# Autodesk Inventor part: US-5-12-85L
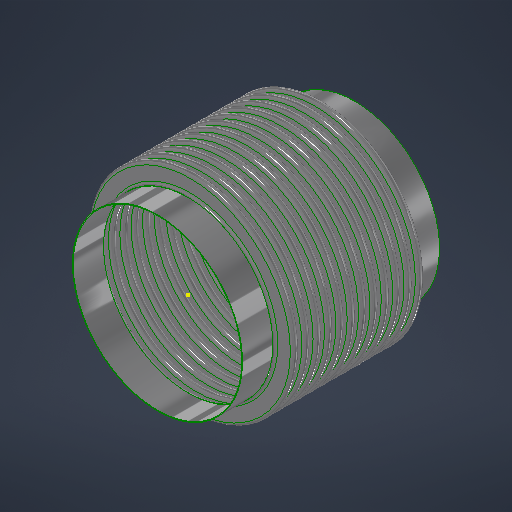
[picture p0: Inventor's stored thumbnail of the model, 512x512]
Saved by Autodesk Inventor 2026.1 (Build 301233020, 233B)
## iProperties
Category: 24 GA (0.024 THICK)
RuleStatus: InUse
Created: 2026-07
Part Number: US-5-12-85L
Project: =STOCK BELLOWS: <Stock Number><SFILL>
Material: ASTM A240-304
Description: =STOCK BELLOWS: <Stock Number>, <SID_> I.D., <SOD_> O.D., <SPLY_> PLY, <Category>, <SNET_CONS> CONS.<PITCH_><STANGENT_> TANGENT<SFILL>
Document SubType Name: Sheet Metal
Designer: LC
Stock Number: U.S-5-12-85L
Surface Area: 659.127 cm^2
Volume: 56.61 cm^3
Sheet Metal Rule: Default
Appearance: STAINLESS STEEL
NET_TUBE: 3.428
COUNTER: 1.500
PBAR: 1.214
PSET: 5.356
PLY: 2
CONS: 2
THK: 0.036
ID: 4.500
OD: 5.500
CONS_: 2
TANGENT: 0.500
PITCH: 0.375
BELLOWS_UPSET: 0.000
NET_CONS: 2
S_CONS: 0
Description_Units: 0
ID_M: 114.30 mm
OD_M: 139.70 mm
THK_M: 0.91 mm
ID_U: 4.500 in
OD_U: 5.500 in
THK_U: 0.036 in
TANGENT2: 0.500
d79: 1.000
d82: 1.000
d83: 26.000
d84: 24.000
d80: 2.571
d81: 10
SID: 2.375
SCONS_: 12
SPITCH: 0.250
SBELLOWS_UPSET: 0.000
SNET_CONS: 12
SS_CONS: 0
SCONS: 8
d174: 8
d177: 0.018
d178: 2.375
d179: 3.000
d180: 0.375
d181: 1.000
d182: 0.000
d190: 8
d191: 1
d192: 1
d193: 8
d194: 0
PART_NUMBER: U.S-5-12-85L
PRESSURE: 85
SIZE: 5.00
STANGENT_: 1.000
d214: 8
d217: 0.030
d218: 6.625
d219: 8.125
d220: 0.500
d221: 1.000
d222: 0.000
d230: 8
d231: 1
d232: 1
d233: 8
d234: 0
STANGENT: 4.000
SPLY_: 1
STHK_: 0.024
SID_: 5.563
SOD_: 6.813
SPITCH_: 0.375
STANGENT__: 1.000
SBELLOWS_UPSET_: 0.000
SDIFF_TAN: 1.000
TAN_TO_TAN: 0.750 in
d252: 2
d275: 2
d287: 0.050
d289: 0.500
d290: 0.000
d263: 2
d265: 1
d268: 2
d269: 0
d286: 2
d288: 1
d291: 2
d292: 0
SOD_NECK: 5 5/8
CFILL: .
SFILL: .
PITCH_: =, <SPITCH_> PITCH,
SREROLL: 0.750
MATTABLE: 20 GA (0.036 THICK)
MESH: ,
CSECT: 2
Author: LC
Keywords: 20 GA (0.036 THICK)
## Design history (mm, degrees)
sketch "Sketch2"
  geometry: L1 (0, -183.595)-(0, 600.956) reference; L2 (58.979, 0)-(57.15, 0); L3 (60.446, -1.467)-(66.554, -1.467); L4 (60.446, -3.296)-(66.554, -3.296); L5 (66.554, -8.058)-(60.446, -8.058); L6 (66.554, -6.229)-(60.446, -6.229); L7 (58.979, -9.525)-(57.15, -9.525); L8 (60.446, 0)-(60.446, -9.525); L9 (66.554, -4.762)-(69.85, -4.763); L10 (57.15, 0)-(57.15, -9.525); L11 (20.376, 102.841)-(20.376, 101.926); L12 (58.262, 488.877)-(58.262, 349.177); L13 (58.262, 479.352)-(58.262, 339.652); L14 (93.133, -58.817)-(93.133, -71.517); L15 (118.746, -66.401)-(118.746, -66.401); L16 (66.554, -6.229)-(66.554, -8.058); L17 (60.446, -6.229)-(60.446, -8.058); L18 (60.446, -7.144)-(66.554, -7.144); L19 (69.85, 0)-(69.85, -9.525); L20 (-66.554, -6.229)-(-66.554, -8.058); L21 (-66.554, -1.467)-(-60.446, -1.467); L22 (-66.554, -3.296)-(-60.446, -3.296); L23 (-60.446, -6.229)-(-66.554, -6.229); L24 (-66.554, -7.144)-(-60.446, -7.144); L25 (-60.446, -8.058)-(-66.554, -8.058); L26 (-60.446, -6.229)-(-60.446, -8.058); L27 (-57.15, -2.522)-(-57.15, -12.047); L28 (-60.446, -4.763)-(-57.15, -4.763); L29 (-66.554, 3.828)-(-66.554, -9.525); L30 (-68.021, 0)-(-69.85, 0); L31 (-69.85, 0)-(-69.85, -9.525); L32 (-68.021, -9.525)-(-69.85, -9.525); A1 r 1.467 centre (60.446, 0) between (58.979, 0) and (60.446, -1.467); A2 r 3.296 centre (60.446, 0) between (57.15, 0) and (60.446, -3.296); A3 r 3.296 centre (66.554, -4.762) between (66.554, -8.058) and (66.554, -1.467); A4 r 1.467 centre (66.554, -4.762) between (66.554, -6.229) and (66.554, -3.296); A5 r 1.467 centre (60.446, -9.525) between (60.446, -8.058) and (58.979, -9.525); A6 r 3.296 centre (60.446, -9.525) between (60.446, -6.229) and (57.15, -9.525); A7 r 2.381 centre (66.554, -4.762) between (66.554, -7.144) and (68.936, -4.762); A8 r 2.381 centre (60.446, -9.525) between (60.446, -7.144) and (58.064, -9.525); A9 r 1.467 centre (-66.554, -9.525) between (-66.554, -8.058) and (-68.021, -9.525); A10 r 1.467 centre (-60.446, -4.763) between (-60.446, -6.229) and (-60.446, -3.296); A11 r 2.381 centre (-60.446, -4.763) between (-60.446, -7.144) and (-58.064, -4.763); A12 r 3.296 centre (-60.446, -4.763) between (-60.446, -8.058) and (-60.446, -1.467); A13 r 2.381 centre (-66.554, -9.525) between (-66.554, -7.144) and (-68.936, -9.525); A14 r 3.296 centre (-66.554, -9.525) between (-66.554, -6.229) and (-69.85, -9.525); A15 r 1.467 centre (-66.554, 0) between (-68.021, 0) and (-66.554, -1.467); A16 r 3.296 centre (-66.554, 0) between (-69.85, 0) and (-66.554, -3.296); 10 further points
  constraints: 62 end point, 38 point on circle, 20 tangent, 16 centre point, 12 parallel, 9 midpoint, 7 vertical, 6 coincident, 6 concentric, 6 point on line, 4 equal radius, 4 perpendicular, 3 horizontal, 1 collinear, 1 horizontal alignment, 10 other
  dimensions: "THK" = 0.9144 distance of L11.start L11.end; "ID" = 114.3 distance of L11.end point (20.376, -12.374); "OD" = 139.7 distance of L12.start L12.end; "PITCH" = 9.525 distance of L12.start L13.start; "TANGENT" = 12.7 distance of L14.start L14.end; "BELLOWS_UPSET" = 0 distance of L15.start L15.end; "d43" = 114.3 diameter of L10 L1 (= ID); "d44" = 139.7 diameter of L9.end L1 (= OD); "d45" = 1.8288 distance between parallel lines of L5 L6 (computed from THK, PLY); "d46" = 3.29565 radius of A3 (computed from PITCH, THK, PLY); "UPSET_PITCH" = 9.525 distance of L2.end L7.end (derived); "SIDEWALL_ANGLE" = 0 deg angle of L3 L9 (derived); "CON_GAP" = 2.9337 distance of point (60.446, -6.229) point (60.446, -3.296) (derived); "TAN1" = 3.74046 dimension on A8 (derived); "TAN2" = 3.74046 dimension on A7 (derived); "LEG1" = 6.1087 distance of L18.start L18.end (derived); "d278" = 1.8288 distance between parallel lines of L25 L23 (derived); "d279" = 3.29565 radius of A12 (derived); "d280" = 9.525 distance of L30.end L31.end (derived); "d281" = 360 deg dimension on L21 L28 (derived); "d282" = 2.9337 distance of point (-66.554, -6.229) point (-66.554, -3.296) (derived); "d283" = 3.74046 dimension on A13 (derived); "d284" = 3.74046 dimension on A11 (derived); "d285" = 6.1087 distance of L24.start L24.end (derived); "d293" = 114.3 diameter of L27 L1 (derived); "d294" = 139.7 diameter of L31 L1 (derived)
  node "Sketch Rectangular Pattern1" dims "d31" = 25.4, "ID" = 114.3
  node "Sketch Rectangular Pattern2" dims "d39" = 25.4, "PITCH" = 9.525
revolve "CONS" stored, may be unused: angle "d48" = 90 deg
node "BELLOW MIDPLANE"
pattern_linear "Rectangular Pattern2" dims "d52" = 9.525 (= UPSET_PITCH)
sketch "Sketch5"
  geometry: C1 r 58.979 at (0, 0) reference; C2 r 57.15 at (0, 0) reference
extrude "TANGENT" new body sketch "Sketch5" distance "d53" = 12.7 (= TANGENT); taper "d54" = 0 deg
revolve "SAMETAN" stored, may be unused: angle "d65" = 90 deg
revolve "DIFFTAN" stored, may be unused: angle "d70" = 90 deg
sketch "Sketch9"
  geometry: L1 (58.391, 0)-(-58.391, 0) reference; L2 (0, -17.78)-(0, 17.78) reference; L3 (41.708, 0)-(-41.708, 0); L4 (41.708, -11.906)-(41.708, 11.906); L5 (29.008, -11.906)-(29.008, 11.906); L6 (15.418, 11.906)-(15.418, -11.906); L7 (-29.008, -11.906)-(-29.008, 11.906); L8 (-41.708, -11.906)-(-41.708, 11.906); L9 (40.914, -11.906)-(40.914, 11.906); L10 (41.708, -11.906)-(40.914, -11.906); L11 (41.708, 11.906)-(40.914, 11.906); L12 (15.815, 11.906)-(15.022, 11.906); L13 (15.022, 11.906)-(15.022, -11.906); L14 (15.022, -11.906)-(15.815, -11.906); L15 (15.815, -11.906)-(15.815, 11.906); L16 (-15.815, 11.906)-(-15.815, -11.906); L17 (-15.418, 11.906)-(-15.418, -11.906); L18 (-15.815, -11.906)-(-15.022, -11.906); L19 (-15.022, -11.906)-(-15.022, 11.906); L20 (-15.022, 11.906)-(-15.815, 11.906); L21 (-41.708, -11.906)-(-40.914, -11.906); L22 (-40.914, -11.906)-(-40.914, 11.906); L23 (-40.914, 11.906)-(-41.708, 11.906); L24 (-41.708, 11.906)-(-41.708, -11.906); L25 (41.708, -0.397)-(-41.708, -0.397); L26 (-41.708, -0.397)-(-41.708, 0.397); L27 (-41.708, 0.397)-(41.708, 0.397); L28 (41.708, 0.397)-(41.708, -0.397); L29 (-41.708, 11.906)-(41.708, 11.906); L30 (41.708, 11.906)-(41.708, 12.7); L31 (41.708, 12.7)-(-41.708, 12.7); L32 (-41.708, 12.7)-(-41.708, 11.906); L33 (41.708, -11.906)-(-41.708, -11.906); L34 (-41.708, -11.906)-(-41.708, -12.7); L35 (-41.708, -12.7)-(41.708, -12.7); L36 (41.708, -12.7)-(41.708, -11.906); 30 further points
  constraints: 68 end point, 13 midpoint, 13 parallel, 8 horizontal, 7 perpendicular, 6 equal length, 3 point on line, 2 vertical, 14 other
  dimensions: "d115" = 23.8125 distance of L4.start L4.end (derived); "d116" = 12.7 distance between parallel lines of L4 L5 (derived); "d117" = 13.58962 distance between parallel lines of L5 L6 (derived); "d125" = 44.42645 distance between parallel lines of L7 L6 (derived); "d127" = 12.7 distance between parallel lines of L8 L7 (derived); "d128" = 26.28962 distance between parallel lines of L6 L4 (derived); "d130" = 83.41607 distance between parallel lines of L8 L4 (derived); "RULER_THK" = 0.79375 distance between parallel lines of L4 L9; "d135" = 0.79375 distance of L13.end L14.end (derived); "d138" = 30.83684 distance of L13.end L16.end (derived); "d143" = 0.79375 distance of L22.end L8.end (derived); "d144" = 0.79375 distance between parallel lines of L27 L25 (derived)
extrude "RULER" join sketch "Sketch9" distance "d149" = 0.79375 (derived); taper "d150" = 0 deg
extrude "BARS" join sketch "Sketch9" distance "d151" = 0.79375 (derived); taper "d152" = 0 deg
pattern_linear "Rectangular Pattern4" dims "d155" = 30.83684 (derived)
sketch "Sketch13"
  geometry: L1 (93.149, -52.467)-(93.149, -77.867); L2 (71.26, 0)-(70.65, 0); L3 (71.26, -9.525)-(70.65, -9.525); L4 (83.839, -7.449)-(73.336, -7.449); L5 (83.839, -6.839)-(73.336, -6.839); L6 (83.839, -4.763)-(86.525, -4.763); L7 (73.336, -2.076)-(83.839, -2.076); L8 (73.336, 0)-(73.336, -9.525); L9 (70.65, 0)-(70.65, -9.525); L10 (58.254, -341.381)-(58.254, -514.431); L11 (58.254, -350.906)-(58.254, -523.956); L12 (58.254, -369.956)-(58.254, -543.006); L13 (58.254, -379.481)-(58.254, -552.531); L14 (58.254, -389.006)-(58.254, -562.056); L15 (58.254, -398.531)-(58.254, -571.581); L16 (58.254, -408.056)-(58.254, -581.106); L17 (58.254, -360.431)-(58.254, -533.481); L18 (20.376, 102.536)-(20.376, 101.926); L19 (73.336, -2.686)-(83.839, -2.686); L20 (0, -696.234)-(0, 235.664) reference; L21 (-23.752, 0)-(142.514, 0) reference; A1 r 2.076 centre (73.336, 0) between (71.26, 0) and (73.336, -2.076); A2 r 2.076 centre (73.336, -9.525) between (73.336, -7.449) and (71.26, -9.525); A3 r 2.686 centre (73.336, -9.525) between (73.336, -6.839) and (70.65, -9.525); A4 r 2.076 centre (83.839, -4.763) between (83.839, -6.839) and (83.839, -2.686); A5 r 2.686 centre (83.839, -4.763) between (83.839, -7.449) and (83.839, -2.076); A6 r 2.686 centre (73.336, 0) between (70.65, 0) and (73.336, -2.686); 6 further points; 1 other entity
  constraints: 38 end point, 15 point on circle, 9 tangent, 6 centre point, 6 parallel, 5 vertical alignment, 4 point on line, 4 vertical, 3 coincident, 3 concentric, 2 collinear, 2 equal radius, 1 horizontal, 1 perpendicular, 23 other
  dimensions: "SBELLOWS_UPSET_" = 0 distance of point (118.762, -66.401) point (118.762, -66.401); "STOTAL_THK_BELLOW__" = 0.6096 distance between parallel lines of L4 L5 (derived); "d224" = 2.68605 radius of A5 (derived); "d225" = 9.525 distance of L2.end L3.end (derived); "SSIDEWALL_ANGLE_" = 0 deg angle of L7 L6 (derived); "SSCON_GAP_" = 4.1529 distance of point (73.336, -6.839) point (73.336, -2.686) (derived); "d235" = 141.3002 diameter of L9 L20 (derived); "d236" = 173.0502 diameter of L6.end L20 (derived)
  node "Sketch Rectangular Pattern4" dims "d228" = 25.4
  node "Sketch Rectangular Pattern5" dims "d229" = 25.4
revolve "SBELLOW" stored, may be unused: angle "d197" = 90 deg
pattern_linear "Rectangular Pattern5" dims "d204" = 9.525 (derived)
revolve "STANGENT" stored, may be unused: angle "d240" = 90 deg
revolve "SSAMETAN" stored, may be unused: angle "d241" = 90 deg
revolve "SDIFFTAN" stored, may be unused: angle "d246" = 90 deg
revolve "INVCON" stored, may be unused: angle "d295" = 90 deg
pattern_linear "Rectangular Pattern6" dims "d298" = 9.525 (derived)
revolve "INVTANGENT" stored, may be unused: angle "d302" = 90 deg
revolve "INVSAMETAN" stored, may be unused: angle "d307" = 90 deg
revolve "INVDIFFTAN" stored, may be unused: angle "d312" = 90 deg
sketch "ID BELLOW MOUNT CALC"
  geometry: L1 (44.45, 0)-(38.1, 0); L2 (38.1, 0)-(38.1, 12.7); L3 (38.1, 12.7)-(44.45, 12.7); L4 (44.45, 12.7)-(44.45, 0); L5 (36.513, 12.7)-(34.684, 12.7); L6 (34.684, 12.7)-(34.684, 0); L7 (34.684, 0)-(36.513, 0); L8 (36.513, 0)-(36.513, 12.7); L9 (0, -2.54)-(0, 15.24) reference; L10 (-8.89, 0)-(53.34, 0) reference; 1 further point
  constraints: 16 end point, 5 parallel, 2 collinear, 2 horizontal, 2 perpendicular
  dimensions: "d314" = 12.7 distance of L5.end L6.end (derived); "d315" = 1.8288 distance of L5.start L5.end (derived); "IG" = 1.5875 distance between parallel lines of L2 L8; "PIPE_OD" = 88.9 diameter of L4 L9; "PIPE_WALL" = 6.35 distance of L2.end L3.end; "ID_MT_BELLOW" = 69.3674 diameter of L6 L9 (derived)
revolve "CFILL" stored, may be unused: angle "d320" = 90 deg
pattern_linear "Rectangular Pattern7" dims "d323" = 9.525 (derived)
revolve "SFILL" stored, may be unused: angle "d324" = 90 deg
pattern_linear "Rectangular Pattern8" dims "d327" = 9.525 (derived)
node "STOCK BELLOW MIDPLANE"
sketch "Sketch21"
  geometry: L1 (0, -100.013)-(0, 100.013) reference; L2 (-100.013, 0)-(100.013, 0) reference; L3 (-0.099, 71.437)-(0.099, 71.437); L4 (0.099, 71.437)-(0.099, 55.562); L5 (0.099, 55.562)-(-0.099, 55.562); L6 (-0.099, 55.562)-(-0.099, 71.437); C1 r 55.562 at (0, 0); C2 r 71.437 at (0, 0); 3 further points
  constraints: 8 end point, 2 centre point, 2 coincident, 2 parallel, 2 tangent, 1 horizontal, 1 perpendicular, 1 other
  dimensions: "d329" = 111.125 diameter of C1 (derived); "d330" = 142.875 diameter of C2 (derived); "d331" = 0.19844 distance of L3.start L3.end
extrude "CLAMSHELL" cut sketch "Sketch21" extent not by distance; stored distance "d332" = 0; taper "d333" = 0 deg
pattern_circular "Circular Pattern1" dims angle "d335" = 180 deg (derived)
node "BELLOW"
sketch "Sketch6"
  geometry: L1 (-19.05, 58.979)-(-6.35, 58.979); L2 (-6.35, 58.979)-(-6.35, 57.15); L3 (-6.35, 57.15)-(-19.05, 57.15); L4 (-19.05, 57.15)-(-19.05, 58.979); L5 (2.54, 0)-(-59.69, 0) reference; L6 (-38.1, -108.388)-(-38.1, 156.601) reference; 1 further point
  constraints: 8 end point, 2 parallel, 1 horizontal, 1 perpendicular
  dimensions: "d61" = 12.7 distance of L2.end L3.end (derived); "d62" = 1.8288 distance of L1.end L2.end (derived); "d63" = 114.3 diameter of L3 L5 (derived); "d64" = 19.05 distance between parallel lines of L4 L6 (derived)
sketch "Sketch12"
  geometry: 1 further point
sketch "Sketch14"
  geometry: L1 (-25.4, 71.26)-(0, 71.26); L2 (0, 71.26)-(0, 70.65); L3 (0, 70.65)-(-25.4, 70.65); L4 (-25.4, 70.65)-(-25.4, 71.26); L5 (5.08, 0)-(-30.48, 0) reference; L6 (0, -11.552)-(0, 69.312) reference; 1 further point
  constraints: 8 end point, 2 parallel, 1 collinear, 1 horizontal, 1 perpendicular
  dimensions: "d237" = 0.6096 distance of L3.end L1.start (derived); "d238" = 141.3002 diameter of L3 L5 (derived); "d239" = 25.4 distance of L1.start L1.end (derived); "SOD_NECK" = 142.5194 diameter of L1 L5 (derived)
sketch "Sketch15"
  geometry: L1 (-11.552, 0)-(69.312, 0) reference; L2 (70.65, -114.3)-(71.26, -114.3); L3 (71.26, -114.3)-(71.26, -139.7); L4 (71.26, -139.7)-(70.65, -139.7); L5 (70.65, -139.7)-(70.65, -114.3); L6 (0, -170.18)-(0, 43.18) reference; 1 further point
  constraints: 8 end point, 2 parallel, 1 horizontal, 1 perpendicular
  dimensions: "d205" = 25.4 distance of L4.end L2.start (derived); "d206" = 0.6096 distance of L3.end L4.end (derived); "d207" = 141.3002 diameter of L5 L6 (derived); "d208" = 114.3 distance between parallel lines of L1 L2 (derived)
node "TANGENT_"
node "SAME_TAN"
sketch "Sketch8"
  geometry: L1 (58.979, -19.05)-(57.15, -19.05); L2 (57.15, -19.05)-(57.15, -31.75); L3 (57.15, -31.75)-(58.979, -31.75); L4 (58.979, -31.75)-(58.979, -19.05); L5 (0, -40.64)-(0, 21.59) reference; L6 (-108.388, 0)-(156.601, 0) reference; 1 further point
  constraints: 8 end point, 2 parallel, 1 horizontal, 1 perpendicular
  dimensions: "d66" = 114.3 diameter of L2 L5 (derived); "TOTAL_THK_BELLOW" = 1.8288 distance of L2.end L3.end (derived); "d68" = 19.05 distance between parallel lines of L1 L6 (derived); "d69" = 12.7 distance of L1.end L2.end (derived)
node "DIFF_TAN"
node "Sketch Rectangular Pattern3" dims "d138" = 30.83684 (derived), "d141" = 25.4
node "SBELLOW_"
node "STANGENT_"
node "SSAME_TAN"
sketch "Sketch16"
  geometry: L1 (71.26, -114.3)-(70.65, -114.3); L2 (70.65, -114.3)-(70.65, -139.7); L3 (70.65, -139.7)-(71.26, -139.7); L4 (71.26, -139.7)-(71.26, -114.3); L5 (0, -170.18)-(0, 43.18) reference; L6 (-11.552, 0)-(69.312, 0) reference; 1 further point
  constraints: 8 end point, 2 parallel, 1 horizontal, 1 perpendicular
  dimensions: "SDIFF_TAN" = 25.4 distance of L3.end L1.start; "d243" = 0.6096 distance of L2.end L3.end (derived); "d244" = 114.3 distance between parallel lines of L1 L6 (derived); "d245" = 141.3002 diameter of L2 L5 (derived)
node "SDIFF_TAN"
body "Solid15"
sketch "Sketch17"
  geometry: L1 (69.85, 12.7)-(68.021, 12.7); L2 (68.021, 12.7)-(68.021, 0); L3 (68.021, 0)-(69.85, 0); L4 (69.85, 0)-(69.85, 12.7); L5 (0, -2.54)-(0, 15.24) reference; L6 (-13.97, 0)-(83.82, 0) reference; 2 further points
  constraints: 8 end point, 2 parallel, 1 horizontal, 1 midpoint, 1 perpendicular, 1 point on line
  dimensions: "INVTANGENT" = 12.7 distance of L3.end L1.start (derived); "d300" = 1.8288 distance of L1.start L1.end (derived); "d301" = 139.7 diameter of L4 L5 (derived)
body "Solid16"
sketch "Sketch18"
  geometry: L1 (69.85, -19.05)-(68.021, -19.05); L2 (68.021, -19.05)-(68.021, -31.75); L3 (68.021, -31.75)-(69.85, -31.75); L4 (69.85, -31.75)-(69.85, -19.05); L5 (-13.97, 0)-(83.82, 0) reference; L6 (0, -40.64)-(0, 21.59) reference; 1 further point
  constraints: 8 end point, 2 parallel, 1 horizontal, 1 perpendicular
  dimensions: "d303" = 19.05 distance between parallel lines of L1 L5 (derived); "d304" = 12.7 distance of L3.end L1.start (derived); "d305" = 1.8288 distance of L2.end L3.end (derived); "d306" = 139.7 diameter of L4 L6 (derived)
body "Solid17"
sketch "Sketch19"
  geometry: L1 (69.85, -19.05)-(68.021, -19.05); L2 (68.021, -19.05)-(68.021, -31.75); L3 (68.021, -31.75)-(69.85, -31.75); L4 (69.85, -31.75)-(69.85, -19.05); L5 (0, -40.64)-(0, 21.59) reference; L6 (-13.97, 0)-(83.82, 0) reference; 1 further point
  constraints: 8 end point, 2 parallel, 1 horizontal, 1 perpendicular
  dimensions: "d308" = 12.7 distance of L1.end L2.end (derived); "d309" = 139.7 diameter of L4 L5 (derived); "d310" = 1.8288 distance of L2.end L3.end (derived); "d311" = 19.05 distance between parallel lines of L1 L6 (derived)
body "Solid18"
body "Solid19"
body "Solid20"
other parameters: "BMPL" = -57.15, "PSET" = 136.0424 (computed from OD, THK, PLY) [user parameter], "PBAR" = 30.83684 (= 0.570796 x PITCH + OD - ID) [user parameter; used in 1 equation term], "COUNTER" = 15 [user parameter], "NET_TUBE" = 87.07367 (computed from CONS_, PBAR, TANGENT) [user parameter], "S_CONS" = 0 [user parameter; used in 1 equation term], "ID_M" = 114.3 (= ID) [user parameter], "OD_M" = 139.7 (= OD) [user parameter], "THK_M" = 0.9144 (= THK) [user parameter], "ID_U" = 114.3 (= ID) [user parameter], "OD_U" = 139.7 (= OD) [user parameter], "THK_U" = 0.9144 (= THK) [user parameter], "D_UNITS" = 0 [user parameter], "TANGENT2" = 12.7 [user parameter], "TAN_TO_TAN" = 19.05 [user parameter], "OD_NECK" = 117.9576 [user parameter], "d79" = 25.4, "d80" = 65.29823 [user parameter], "d82" = 25.4, "d83" = 660.4, "d84" = 609.6, "sa_0" = 4, "FRAME_THK" = 0.79375 [user parameter], "CON_FLAT" = 13.58962 [user parameter], "SID" = 60.325 [user parameter], "SPITCH" = 6.35 [user parameter], "STANGENT_" = 25.4 [user parameter], "SBELLOWS_UPSET" = 0 [user parameter], "SS_CONS" = 0 [user parameter], "STAN_TO_TAN_" = 114.3 [user parameter], "d100" = 0.6096 [user parameter], "d191" = 25.4 [user parameter], "d194" = 0 [user parameter], "STANGENT" = 101.6 [user parameter], "d234" = 0 [user parameter], "SUPSET_PITCH_" = 9.525 [user parameter], "d269" = 0 [user parameter], "d287" = 1.27, "d289" = 12.7, "d290" = 0, "d292" = 0 [user parameter], "Thickness" = 3.048 (derived), "KFactor" = 4.4, "BendRadius" = 3.048 (derived), "BendReliefWidth" = 3.048 (derived), "BendReliefDepth" = 1.524 (derived), "CornerReliefSize" = 12.192 (derived), "SeamGap" = 0.00508, "MinimumRemnant" = 6.096 (derived), "TransitionRadius" = 3.048 (derived), "JacobiRadiusSize" = 3.048 (derived), "GapSize" = 3.048 (derived), "SREROLL" = 19.05 [user parameter], "CUR_STK_PITCH" = 9.525 [user parameter], "d328" = -57.15 (derived), "CSECTDEG" = 180 deg [user parameter]
